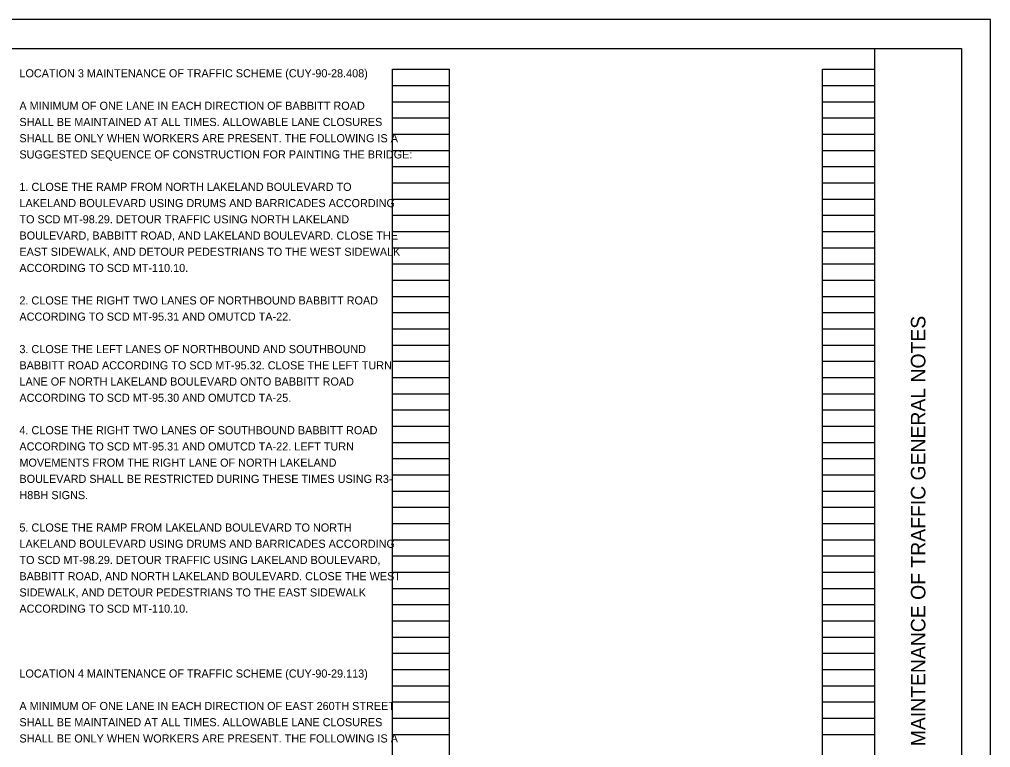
# Model space of a CAD drawing. Extents: x 0 to 34, y 0 to 22.
# Drawn here: x 17.24 to 34, y 9.43 to 22 of the extents above; entities that cross this region are included whole.
import ezdxf

# ---------------------------------------------------------------- set-up
doc = ezdxf.new("R2010")
doc.units = 0
for name, color, linetype in [('SH_Border', 7, 'Continuous'), ('SH_Cut_Line', 7, 'Continuous'), ('SH_Data', 7, 'Continuous'), ('SH_Text', 7, 'Continuous')]:
    doc.layers.add(name, color=color, linetype=linetype)

msp = doc.modelspace()

# ---------------------------------------------------------------- linework, layer by layer
at = {"layer": 'SH_Border'}
msp.add_line((32, 0.5), (32, 21.5), dxfattribs=at)
msp.add_lwpolyline([(1.5, 21.5), (33.5, 21.5), (33.5, 0.5), (1.5, 0.5)], close=True, dxfattribs=at)
at = {"layer": 'SH_Cut_Line'}
msp.add_lwpolyline([(0, 0), (34, 0), (34, 22), (0, 22)], close=True, dxfattribs=at)
at = {"layer": 'SH_Data'}
for p, q in [((23.68, 0.98), (23.68, 21.14)), ((23.68, 21.14), (24.66, 21.14)), ((24.66, 0.98), (24.66, 21.14)), ((31.1, 0.98), (31.1, 21.14)), ((31.1, 21.14), (32, 21.14)), ((32, 0.98), (32, 21.14)), ((23.68, 20.86), (24.66, 20.86)), ((31.1, 20.86), (32, 20.86)), ((23.68, 20.58), (24.66, 20.58)), ((31.1, 20.58), (32, 20.58)), ((23.68, 20.3), (24.66, 20.3)), ((31.1, 20.3), (32, 20.3)), ((23.68, 20.02), (24.66, 20.02)), ((31.1, 20.02), (32, 20.02)), ((23.68, 19.74), (24.66, 19.74)), ((31.1, 19.74), (32, 19.74)), ((23.68, 19.46), (24.66, 19.46)), ((31.1, 19.46), (32, 19.46)), ((23.68, 19.18), (24.66, 19.18)), ((31.1, 19.18), (32, 19.18)), ((23.68, 18.9), (24.66, 18.9)), ((31.1, 18.9), (32, 18.9)), ((23.68, 18.62), (24.66, 18.62)), ((31.1, 18.62), (32, 18.62)), ((23.68, 18.34), (24.66, 18.34)), ((31.1, 18.34), (32, 18.34)), ((23.68, 18.06), (24.66, 18.06)), ((31.1, 18.06), (32, 18.06)), ((23.68, 17.78), (24.66, 17.78)), ((31.1, 17.78), (32, 17.78)), ((23.68, 17.5), (24.66, 17.5)), ((31.1, 17.5), (32, 17.5)), ((23.68, 17.22), (24.66, 17.22)), ((31.1, 17.22), (32, 17.22)), ((23.68, 16.94), (24.66, 16.94)), ((31.1, 16.94), (32, 16.94)), ((23.68, 16.66), (24.66, 16.66)), ((31.1, 16.66), (32, 16.66)), ((23.68, 16.38), (24.66, 16.38)), ((31.1, 16.38), (32, 16.38)), ((23.68, 16.1), (24.66, 16.1)), ((31.1, 16.1), (32, 16.1)), ((23.68, 15.82), (24.66, 15.82)), ((31.1, 15.82), (32, 15.82)), ((23.68, 15.54), (24.66, 15.54)), ((31.1, 15.54), (32, 15.54)), ((23.68, 15.26), (24.66, 15.26)), ((31.1, 15.26), (32, 15.26)), ((23.68, 14.98), (24.66, 14.98)), ((31.1, 14.98), (32, 14.98)), ((23.68, 14.7), (24.66, 14.7)), ((31.1, 14.7), (32, 14.7)), ((23.68, 14.42), (24.66, 14.42)), ((31.1, 14.42), (32, 14.42)), ((23.68, 14.14), (24.66, 14.14)), ((31.1, 14.14), (32, 14.14)), ((23.68, 13.86), (24.66, 13.86)), ((31.1, 13.86), (32, 13.86)), ((23.68, 13.58), (24.66, 13.58)), ((31.1, 13.58), (32, 13.58)), ((23.68, 13.3), (24.66, 13.3)), ((31.1, 13.3), (32, 13.3)), ((23.68, 13.02), (24.66, 13.02)), ((31.1, 13.02), (32, 13.02)), ((23.68, 12.74), (24.66, 12.74)), ((31.1, 12.74), (32, 12.74)), ((23.68, 12.46), (24.66, 12.46)), ((31.1, 12.46), (32, 12.46)), ((23.68, 12.18), (24.66, 12.18)), ((31.1, 12.18), (32, 12.18)), ((23.68, 11.9), (24.66, 11.9)), ((31.1, 11.9), (32, 11.9)), ((23.68, 11.62), (24.66, 11.62)), ((31.1, 11.62), (32, 11.62)), ((23.68, 11.34), (24.66, 11.34)), ((31.1, 11.34), (32, 11.34)), ((23.68, 11.06), (24.66, 11.06)), ((31.1, 11.06), (32, 11.06)), ((23.68, 10.78), (24.66, 10.78)), ((31.1, 10.78), (32, 10.78)), ((23.68, 10.5), (24.66, 10.5)), ((31.1, 10.5), (32, 10.5)), ((23.68, 10.22), (24.66, 10.22)), ((31.1, 10.22), (32, 10.22)), ((23.68, 9.94), (24.66, 9.94)), ((31.1, 9.94), (32, 9.94)), ((23.68, 9.66), (24.66, 9.66)), ((31.1, 9.66), (32, 9.66))]:
    msp.add_line(p, q, dxfattribs=at)

# ---------------------------------------------------------------- texts
msp.add_text('MAINTENANCE OF TRAFFIC GENERAL NOTES', height=0.25, rotation=90, dxfattribs=at).set_placement((32.875, 9.455))
at = {"layer": 'SH_Text'}
for s, p in [('LOCATION 3 MAINTENANCE OF TRAFFIC SCHEME (CUY-90-28.408)', (17.24, 21)), ('A MINIMUM OF ONE LANE IN EACH DIRECTION OF BABBITT ROAD ', (17.24, 20.44)), ('SHALL BE MAINTAINED AT ALL TIMES. ALLOWABLE LANE CLOSURES  ', (17.24, 20.16)), ('SHALL BE ONLY WHEN WORKERS ARE PRESENT. THE FOLLOWING IS A ', (17.24, 19.88)), ('SUGGESTED SEQUENCE OF CONSTRUCTION FOR PAINTING THE BRIDGE:', (17.24, 19.6)), ('1. CLOSE THE RAMP FROM NORTH LAKELAND BOULEVARD TO ', (17.24, 19.04)), ('LAKELAND BOULEVARD USING DRUMS AND BARRICADES ACCORDING ', (17.24, 18.76)), ('TO SCD MT-98.29. DETOUR TRAFFIC USING NORTH LAKELAND ', (17.24, 18.48)), ('BOULEVARD, BABBITT ROAD, AND LAKELAND BOULEVARD. CLOSE THE ', (17.24, 18.2)), ('EAST SIDEWALK, AND DETOUR PEDESTRIANS TO THE WEST SIDEWALK ', (17.24, 17.92)), ('ACCORDING TO SCD MT-110.10.', (17.24, 17.64)), ('2. CLOSE THE RIGHT TWO LANES OF NORTHBOUND BABBITT ROAD ', (17.24, 17.08)), ('ACCORDING TO SCD MT-95.31 AND OMUTCD TA-22.', (17.24, 16.8)), ('3. CLOSE THE LEFT LANES OF NORTHBOUND AND SOUTHBOUND ', (17.24, 16.24)), ('BABBITT ROAD ACCORDING TO SCD MT-95.32. CLOSE THE LEFT TURN ', (17.24, 15.96)), ('LANE OF NORTH LAKELAND BOULEVARD ONTO BABBITT ROAD ', (17.24, 15.68)), ('ACCORDING TO SCD MT-95.30 AND OMUTCD TA-25.', (17.24, 15.4)), ('4. CLOSE THE RIGHT TWO LANES OF SOUTHBOUND BABBITT ROAD ', (17.24, 14.84)), ('ACCORDING TO SCD MT-95.31 AND OMUTCD TA-22. LEFT TURN ', (17.24, 14.56)), ('MOVEMENTS FROM THE RIGHT LANE OF NORTH LAKELAND ', (17.24, 14.28)), ('BOULEVARD SHALL BE RESTRICTED DURING THESE TIMES USING R3-', (17.24, 14)), ('H8BH SIGNS.', (17.24, 13.72)), ('5. CLOSE THE RAMP FROM LAKELAND BOULEVARD TO NORTH ', (17.24, 13.16)), ('LAKELAND BOULEVARD USING DRUMS AND BARRICADES ACCORDING ', (17.24, 12.88)), ('TO SCD MT-98.29. DETOUR TRAFFIC USING LAKELAND BOULEVARD, ', (17.24, 12.6)), ('BABBITT ROAD, AND NORTH LAKELAND BOULEVARD. CLOSE THE WEST ', (17.24, 12.32)), ('SIDEWALK, AND DETOUR PEDESTRIANS TO THE EAST SIDEWALK ', (17.24, 12.04)), ('ACCORDING TO SCD MT-110.10.', (17.24, 11.76)), ('LOCATION 4 MAINTENANCE OF TRAFFIC SCHEME (CUY-90-29.113)', (17.24, 10.64)), ('A MINIMUM OF ONE LANE IN EACH DIRECTION OF EAST 260TH STREET ', (17.24, 10.08)), ('SHALL BE MAINTAINED AT ALL TIMES. ALLOWABLE LANE CLOSURES ', (17.24, 9.8)), ('SHALL BE ONLY WHEN WORKERS ARE PRESENT. THE FOLLOWING IS A ', (17.24, 9.52))]:
    msp.add_text(s, height=0.14, dxfattribs=at).set_placement(p)

doc.saveas('drawing.dxf')
